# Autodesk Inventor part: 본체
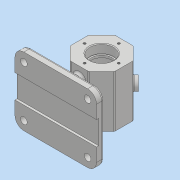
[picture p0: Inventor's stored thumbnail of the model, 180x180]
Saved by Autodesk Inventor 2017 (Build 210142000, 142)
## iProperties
Part Number: 본체
Material: 일반
Document SubType Name: Modeling
Designer: MRC
Density: 1 g/cm^3
Appearance: 기본값
Author: MRC
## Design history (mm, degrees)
sketch "스케치1"
  geometry: L1 (30, 12.426)-(30, -12.426); L2 (30, -12.426)-(12.426, -30); L3 (12.426, -30)-(-12.426, -30); L4 (-12.426, -30)-(-30, -12.426); L5 (-30, -12.426)-(-30, 12.426); L6 (-30, 12.426)-(-12.426, 30); L7 (-12.426, 30)-(12.426, 30); L8 (12.426, 30)-(30, 12.426); 2 further points
  constraints: 16 end point, 1 coincident, 1 horizontal, 17 other
  dimensions: "d1" = 60 distance between parallel lines of L3 L7
extrude "돌출1" new body sketch "스케치1" stored distance "d2" = 70; taper "d3" = 0 deg
sketch "스케치3"
  geometry: 2 further points
  constraints: 1 vertical alignment
  dimensions: "d4" = 23 distance of point (0, 0) point (0, 23)
hole "구멍1" sketch "스케치3" at (0, 23) diameter "d5" = 3.242; stored, may be unused: countersink angle "d9" = 90 deg, drill point angle "d11" = 118 deg; dims "d6" = 8, "d7" = 32, "d8" = 12, "d10" = 10
sketch "스케치4"
  geometry: 2 further points
  constraints: 1 coincident
hole "구멍2" sketch "스케치4" at (0, 0) diameter "d12" = 28; stored, may be unused: countersink angle "d16" = 90 deg, drill point angle "d18" = 0 deg; dims "d13" = 8, "d14" = 32, "d15" = 12, "d17" = 10
sketch "스케치5"
  geometry: C1 r 25 at (0, 0); 1 further point
  constraints: 1 centre point, 1 coincident
  dimensions: "d19" = 50 diameter of C1
extrude "돌출2" cut sketch "스케치5" stored distance "d20" = 40; taper "d21" = 0 deg
sketch "스케치7"
  geometry: C1 r 8 at (-12.426, 35); 1 further point
  constraints: 1 centre point, 1 coincident
  dimensions: "d27" = 16 diameter of C1
extrude "돌출3" join sketch "스케치7" distance "d28" = 5; taper "d29" = 0 deg
hole "구멍3" diameter "d32" = 8; stored, may be unused: countersink angle "d36" = 90 deg, drill point angle "d38" = 0 deg; dims "d30" = 10, "d31" = 10, "d33" = 8, "d34" = 32, "d35" = 12, "d37" = 24
sketch "스케치8"
  geometry: L1 (-55, -52)-(55, -52); L2 (55, -52)-(55, -62); L3 (55, -62)-(-55, -62); L4 (-55, -62)-(-55, -52); 2 further points
  constraints: 8 end point, 2 parallel, 1 horizontal, 1 midpoint, 1 perpendicular, 1 vertical alignment
  dimensions: "d39" = 110 distance of L2.end L3.end; "d40" = 10 distance of L1.end L2.end; "d41" = 62 vertical distance of L3.end point (0, 0)
extrude "돌출4" join sketch "스케치8" stored distance "d42" = 92; taper "d43" = 0 deg
sketch "스케치9"
  geometry: L1 (55, 66)-(55, 26); L2 (61, 66)-(61, 26); L3 (49, 26)-(49, 66); A1 r 6 centre (55, 66) between (61, 66) and (49, 66); A2 r 6 centre (55, 26) between (49, 26) and (61, 26); 2 further points
  constraints: 8 end point, 4 point on circle, 4 tangent, 2 centre point, 1 coincident, 1 midpoint, 1 parallel, 1 vertical
  dimensions: "d44" = 40 distance of L1.end L1.start; "d45" = 12 distance between parallel lines of L2 L3
extrude "돌출5" join sketch "스케치9" stored distance "d46" = 92; taper "d47" = 0 deg
fillet "모깎기1" dims "d48" = 12
sketch "스케치10"
  geometry: L1 (-12, 80)-(-12, 12) reference; L2 (86, 0)-(0, 0) reference; L3 (98, 12)-(98, 80) reference; L4 (0, 92)-(86, 92) reference; L5 (37, 26)-(37, 66) reference; L6 (49, 66)-(49, 26) reference; A1 r 12 centre (0, 80) between (0, 92) and (-12, 80) reference; A2 r 12 centre (0, 12) between (-12, 12) and (0, 0) reference; A3 r 12 centre (86, 12) between (86, 0) and (98, 12) reference; A4 r 12 centre (86, 80) between (98, 80) and (86, 92) reference; A5 r 6 centre (43, 26) between (37, 26) and (49, 26) reference; A6 r 6 centre (43, 66) between (49, 66) and (37, 66) reference; 5 further points
  constraints: 4 coincident
hole "구멍4" sketch "스케치10" at (0, 80), (0, 12), (86, 80), (86, 12) diameter "d49" = 9; stored, may be unused: countersink angle "d53" = 90 deg, drill point angle "d55" = 0 deg; dims "d50" = 8, "d51" = 32, "d52" = 12, "d54" = 24
sketch "스케치11"
  geometry: L1 (-68, 0)-(0, 0) reference; L2 (-50, 0)-(-50, 3); L3 (-50, 3)-(-18, 3); L4 (-18, 3)-(-18, 0); 2 further points
  constraints: 6 end point, 3 perpendicular, 2 point on line, 1 midpoint, 1 vertical alignment
  dimensions: "d56" = 32 distance of L2.end L3.end; "d57" = 3 distance of L3.end L4.end
extrude "돌출6" cut sketch "스케치11" stored distance "d58" = 92; taper "d59" = 0 deg
sketch "스케치12"
  geometry: L1 (-17.574, 0)-(-17.574, 70) reference; 2 further points
  constraints: 1 coincident, 1 other
  dimensions: "d60" = 30 distance from line of point (12.426, 35) L1
feature "엠보싱1" sketch "스케치12" dims "d1" = 60, "d61" = 0.5, "d62" = 0
fillet "모깎기2" dims "d63" = 3
fillet "모깎기3" dims "d64" = 3
fillet "모깎기4" dims "d65" = 1
fillet "모깎기5" dims "d66" = 0.3
fillet "모깎기6" dims "d67" = 3
chamfer "모따기1" distance "d68" = 1; stored, may be unused: second distance "d69" = 2, angle "d70" = 45 deg
node "솔리드1"
pattern_circular "원형 패턴1" dims angle "d23" = 360 deg
mirror "미러1"
node "투영된 루프1"
